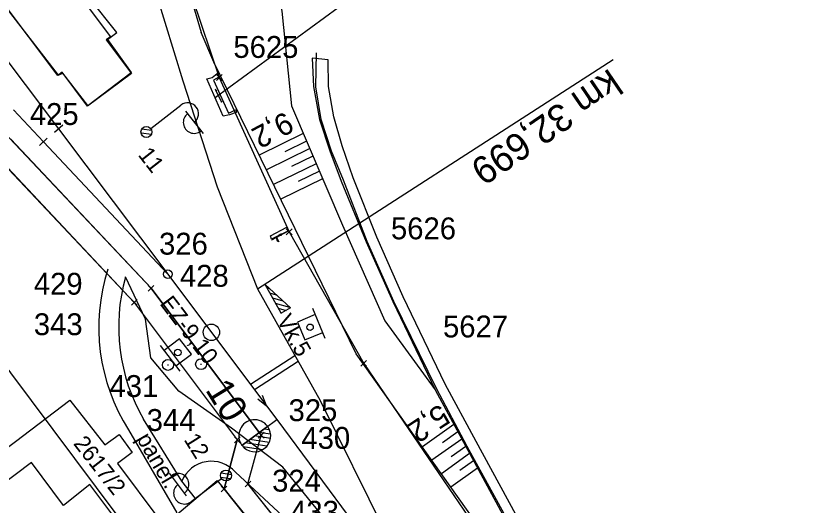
# Model space of a CAD drawing. Extents: x -804166 to -803706, y -1151030 to -1150147.
# Drawn here: x -803925.7 to -803852.1, y -1150474.2 to -1150429.4 of the extents above; entities that cross this region are included whole.
import ezdxf

# ---------------------------------------------------------------- set-up
doc = ezdxf.new("R2010")
doc.units = 0
for name, color, linetype in [('0381KM032-037P - Vrstva 1', 7, 'Continuous'), ('0381KM032-037P - Vrstva 13', 7, 'Continuous'), ('0381KM032-037P - Vrstva 17', 7, 'Continuous'), ('0381KM032-037P - Vrstva 19', 7, 'Continuous'), ('0381KM032-037P - Vrstva 2', 7, 'Continuous'), ('0381KM032-037P - Vrstva 23', 7, 'Continuous'), ('0381KM032-037P - Vrstva 25', 7, 'Continuous'), ('0381KM032-037P - Vrstva 27', 7, 'Continuous'), ('0381KM032-037P - Vrstva 3', 7, 'Continuous'), ('0381KM032-037P - Vrstva 48', 7, 'Continuous'), ('0381KM032-037P - Vrstva 49', 7, 'Continuous'), ('0381KM032-037P - Vrstva 51', 7, 'Continuous'), ('0381KM032-037P - Vrstva 55', 7, 'Continuous'), ('0381KM032-037P - Vrstva 57', 7, 'Continuous'), ('0381KM032-037P - Vrstva 7', 7, 'Continuous'), ('DZ_CD - CD', 7, 'Continuous'), ('DZ_CD - CD_krizek', 7, 'Continuous'), ('DZ_CD - CD_čísla', 7, 'Continuous'), ('szdc - hran DP', 7, 'Continuous'), ('szdc - szdc_cislo', 7, 'Continuous'), ('szdc - szdc_krizek', 7, 'Continuous'), ('VB - VB', 7, 'Continuous'), ('VB - VB_cislo', 7, 'Continuous'), ('VB - VB_krizek', 7, 'Continuous')]:
    doc.layers.add(name, color=color, linetype=linetype)

msp = doc.modelspace()

# ---------------------------------------------------------------- linework, layer by layer
at = {"layer": '0381KM032-037P - Vrstva 1'}
for p, q in [((-803925.981, -1150438.008), (-803923.249, -1150440.918)), ((-803901.897, -1150466.329), (-803893.522, -1150477.59))]:
    msp.add_line(p, q, dxfattribs=at)
for points in [[(-804011.14, -1150262.39), (-804005.45, -1150273.41), (-803998.73, -1150284.85), (-803991.51, -1150295.63), (-803978.8, -1150312.77), (-803963.69, -1150332.99), (-803952.21, -1150348.36), (-803946.3, -1150356.39), (-803941.6, -1150363.14), (-803936.71, -1150370.83), (-803932.05, -1150378.84), (-803927.78, -1150386.91), (-803924.06, -1150395.18), (-803920.62, -1150403.65), (-803918.06, -1150410.86), (-803915.07, -1150420.32), (-803912.96, -1150427.25), (-803910.49, -1150435.34), (-803907.334, -1150445.05), (-803903.668, -1150454.381), (-803897.938, -1150464.596), (-803891.973, -1150476.598)], [(-803975.617, -1150392.296), (-803939.473, -1150444.116), (-803928.265, -1150459.416), (-803914.534, -1150477.731)], [(-803937.129, -1150419.412), (-803921.855, -1150439.729)], [(-803921.855, -1150439.729), (-803911.864, -1150453.035), (-803902.83, -1150465.067), (-803901.897, -1150466.329)], [(-803923.249, -1150440.918), (-803911.864, -1150453.035), (-803902.83, -1150465.067), (-803901.897, -1150466.329)]]:
    msp.add_lwpolyline(points, dxfattribs=at)
at = {"layer": '0381KM032-037P - Vrstva 13'}
msp.add_lwpolyline([(-803875.883, -1150484.91), (-803874.859, -1150484.495), (-803883.662, -1150468.351), (-803886.496, -1150463.09), (-803890.342, -1150455.103), (-803892.739, -1150449.637), (-803894.892, -1150444.207), (-803895.921, -1150441.276), (-803896.676, -1150438.635), (-803897.147, -1150435.872), (-803897.2, -1150433.432), (-803898.654, -1150433.258), (-803898.54, -1150435.86), (-803897.995, -1150438.863), (-803897.041, -1150441.738), (-803895.987, -1150444.528), (-803893.704, -1150450.064), (-803891.289, -1150455.545), (-803887.412, -1150463.602)], close=True, dxfattribs=at)
at = {"layer": '0381KM032-037P - Vrstva 17'}
msp.add_line((-803911.209, -1150475.173), (-803907.336, -1150471.899), dxfattribs=at)
for points in [[(-803875.87, -1150484.459), (-803884.486, -1150468.8), (-803887.25, -1150463.566), (-803891.192, -1150455.528), (-803893.615, -1150450.032), (-803895.787, -1150444.436), (-803896.9, -1150441.761), (-803897.818, -1150438.885), (-803898.314, -1150435.883), (-803898.256, -1150432.783)], [(-803907.336, -1150471.899), (-803888.961, -1150494.568)]]:
    msp.add_lwpolyline(points, dxfattribs=at)
at = {"layer": '0381KM032-037P - Vrstva 19'}
for p, q in [((-803907.537, -1150436.866), (-803852.112, -1150396.222)), ((-803907.526, -1150436.102), (-803907.373, -1150436.242)), ((-803902.473, -1150449.514), (-803900.978, -1150448.743)), ((-803900.834, -1150449.068), (-803902.371, -1150449.816)), ((-803902.35, -1150449.879), (-803900.834, -1150449.068)), ((-803900.978, -1150448.743), (-803900.834, -1150449.068)), ((-803902.371, -1150449.816), (-803902.473, -1150449.514)), ((-803902.371, -1150449.816), (-803902.35, -1150449.879)), ((-803901.816, -1150449.998), (-803901.912, -1150449.697))]:
    msp.add_line(p, q, dxfattribs=at)
for points in [[(-803908.281, -1150435.147), (-803907.8, -1150435.023), (-803907.337, -1150434.681), (-803907.197, -1150434.991), (-803907.689, -1150435.265), (-803906.318, -1150438.295), (-803905.582, -1150437.956), (-803905.605, -1150438.249), (-803906.227, -1150438.463), (-803906.793, -1150438.584), (-803908.281, -1150435.147)], [(-803907.526, -1150436.102), (-803906.954, -1150437.281), (-803906.898, -1150437.161)], [(-803900.834, -1150449.068), (-803900.834, -1150449.068), (-803900.774, -1150449.197)], [(-803901.912, -1150449.697), (-803901.906, -1150449.663), (-803901.715, -1150450.066), (-803901.816, -1150449.998)]]:
    msp.add_lwpolyline(points, dxfattribs=at)
msp.add_ellipse((-803901.564, -1150449.426), major_axis=(0.129, 0.077), ratio=0.428282, dxfattribs=at)
at = {"layer": '0381KM032-037P - Vrstva 2'}
for p, q in [((-803921.481, -1150439.397), (-803922.229, -1150440.061)), ((-803921.855, -1150439.729), (-803911.864, -1150453.035)), ((-803922.888, -1150440.573), (-803923.61, -1150441.263)), ((-803905.077, -1150468.694), (-803901.897, -1150466.329)), ((-803905.085, -1150468.688), (-803902.731, -1150466.949)), ((-803902.453, -1150467.676), (-803903.501, -1150467.519)), ((-803902.551, -1150467.276), (-803903.068, -1150467.199)), ((-803902.579, -1150468.425), (-803904.366, -1150468.157)), ((-803902.467, -1150468.058), (-803903.933, -1150467.837)), ((-803905.084, -1150468.689), (-803905.085, -1150468.688)), ((-803903.204, -1150469.1), (-803904.955, -1150468.837)), ((-803902.804, -1150468.776), (-803904.798, -1150468.476))]:
    msp.add_line(p, q, dxfattribs=at)
for points in [[(-803923.249, -1150440.918), (-803911.864, -1150453.035), (-803901.897, -1150466.329)], [(-803903.617, -1150464.45), (-803902.83, -1150465.067), (-803903.203, -1150464.139)]]:
    msp.add_lwpolyline(points, dxfattribs=at)
msp.add_circle((-803911.864, -1150453.035), 0.4, dxfattribs=at)
for centre, radius, start, end in [((-803903.907, -1150467.817), 1.462, 36.40566, 216.87518), ((-803903.907, -1150467.818), 1.464, 216.49519, 36.45604)]:
    msp.add_arc(centre, radius, start, end, dxfattribs=at)
at = {"layer": '0381KM032-037P - Vrstva 23'}
for p, q in [((-803916.52, -1150430.915), (-803932.913, -1150410.127)), ((-803938.071, -1150413.885), (-803921.901, -1150434.824)), ((-803917.389, -1150431.545), (-803916.52, -1150430.915)), ((-803917.389, -1150431.545), (-803915.2, -1150434.565)), ((-803921.901, -1150434.824), (-803921.458, -1150434.637)), ((-803919.171, -1150437.591), (-803921.458, -1150434.637)), ((-803919.171, -1150437.591), (-803915.2, -1150434.565)), ((-803919.171, -1150437.591), (-803919.171, -1150437.591))]:
    msp.add_line(p, q, dxfattribs=at)
at = {"layer": '0381KM032-037P - Vrstva 25'}
for p, q in [((-803913.427, -1150439.714), (-803910.666, -1150437.563)), ((-803910.235, -1150438.115), (-803908.637, -1150440.166)), ((-803914.313, -1150440.101), (-803913.362, -1150440.219)), ((-803914.23, -1150439.734), (-803913.357, -1150439.842)), ((-803910.152, -1150473.302), (-803911.72, -1150471.228)), ((-803906.046, -1150471.376), (-803906.995, -1150471.244)), ((-803906.938, -1150471.75), (-803909.73, -1150473.861)), ((-803906.134, -1150471.742), (-803907.006, -1150471.621))]:
    msp.add_line(p, q, dxfattribs=at)
for centre in [(-803913.821, -1150440.021), (-803906.539, -1150471.449), (-803906.539, -1150471.449)]:
    msp.add_circle(centre, 0.5, dxfattribs=at)
for centre, start, end in [((-803910.051, -1150438.352), 307.9199, 127.9199), ((-803909.446, -1150439.148), 127.21733, 308.62248), ((-803910.926, -1150472.258), 306.37771, 127.78285), ((-803910.333, -1150473.063), 127.08028, 307.08028)]:
    msp.add_arc(centre, 1, start, end, dxfattribs=at)
at = {"layer": '0381KM032-037P - Vrstva 27'}
msp.add_line((-803908.868, -1150461.265), (-803908.768, -1150461.265), dxfattribs=at)
msp.add_circle((-803908.818, -1150461.265), 0.5, dxfattribs=at)
at = {"layer": '0381KM032-037P - Vrstva 3'}
for p, q in [((-803903.668, -1150454.381), (-803871.126, -1150433.376)), ((-803902.805, -1150454.284), (-803902.575, -1150454.349)), ((-803902.546, -1150454.747), (-803901.955, -1150454.913)), ((-803902.286, -1150455.209), (-803901.335, -1150455.477)), ((-803902.027, -1150455.672), (-803900.714, -1150456.041)), ((-803901.767, -1150456.134), (-803901.031, -1150456.341)), ((-803901.508, -1150456.596), (-803901.493, -1150456.601)), ((-803897.459, -1150458.912), (-803898.603, -1150456.186)), ((-803898.374, -1150456.731), (-803900.01, -1150457.418)), ((-803900.01, -1150457.418), (-803899.323, -1150459.053)), ((-803899.323, -1150459.053), (-803897.688, -1150458.367)), ((-803912.548, -1150459.549), (-803910.758, -1150461.903)), ((-803910.778, -1150458.946), (-803912.19, -1150460.02)), ((-803909.704, -1150460.358), (-803910.778, -1150458.946)), ((-803911.116, -1150461.432), (-803909.704, -1150460.358))]:
    msp.add_line(p, q, dxfattribs=at)
msp.add_lwpolyline([(-803902.97, -1150453.99), (-803900.63, -1150456.117), (-803901.503, -1150456.606), (-803902.97, -1150453.99)], dxfattribs=at)
for centre in [(-803898.85, -1150457.89), (-803910.945, -1150460.191)]:
    msp.add_circle(centre, 0.296, dxfattribs=at)
at = {"layer": '0381KM032-037P - Vrstva 48'}
for p, q in [((-803899.465, -1150440.159), (-803903.499, -1150442.127)), ((-803899.171, -1150440.85), (-803901.17, -1150441.826)), ((-803898.877, -1150441.541), (-803902.841, -1150443.475)), ((-803898.583, -1150442.232), (-803900.547, -1150443.191)), ((-803898.289, -1150442.923), (-803902.183, -1150444.823)), ((-803897.995, -1150443.614), (-803899.924, -1150444.556)), ((-803897.7, -1150444.305), (-803901.525, -1150446.172)), ((-803885.686, -1150466.792), (-803888.569, -1150468.841)), ((-803885.327, -1150467.456), (-803886.73, -1150468.454)), ((-803884.967, -1150468.121), (-803887.7, -1150470.063)), ((-803884.607, -1150468.786), (-803885.936, -1150469.73)), ((-803884.248, -1150469.45), (-803886.831, -1150471.286)), ((-803883.888, -1150470.115), (-803885.142, -1150471.006)), ((-803883.529, -1150470.779), (-803885.962, -1150472.509))]:
    msp.add_line(p, q, dxfattribs=at)
at = {"layer": '0381KM032-037P - Vrstva 49'}
for points in [[(-804010.873, -1150255.863), (-804001.608, -1150274.672), (-803994.699, -1150286.679), (-803981.461, -1150304.357), (-803936.046, -1150366.093), (-803921.768, -1150392.538), (-803912.222, -1150419.282), (-803908.812, -1150430.908)], [(-803920.94, -1150376.21), (-803910.018, -1150390.511), (-803912.553, -1150396.059), (-803903.866, -1150412.95), (-803903.684, -1150418.644), (-803901.421, -1150428.97), (-803900.537, -1150437.639), (-803895.89, -1150448.56), (-803892.01, -1150457.3), (-803887.412, -1150463.602), (-803875.883, -1150484.91), (-803874.859, -1150484.495), (-803872.322, -1150492.497), (-803872.997, -1150496.546), (-803874.041, -1150498.946)], [(-803877.416, -1150484.532), (-803894.615, -1150460.334), (-803907.648, -1150433.624), (-803908.812, -1150430.908)]]:
    msp.add_lwpolyline(points, dxfattribs=at)
at = {"layer": '0381KM032-037P - Vrstva 51'}
for p, q in [((-803915.743, -1150453.306), (-803915.72, -1150453.288)), ((-803915.449, -1150467.279), (-803911.051, -1150474.867)), ((-803900.893, -1150475.608), (-803905.683, -1150471.142))]:
    msp.add_line(p, q, dxfattribs=at)
for points in [[(-803881.519, -1150497.913), (-803892.597, -1150481.46), (-803901.351, -1150470.694), (-803906.021, -1150467.127), (-803910.842, -1150463.746), (-803913.43, -1150460.674), (-803913.908, -1150457.138), (-803915.72, -1150453.288)], [(-803909.318, -1150473.555), (-803910.58, -1150471.975), (-803914.083, -1150466.31)]]:
    msp.add_lwpolyline(points, dxfattribs=at)
for centre, major_axis, ratio, start_param, end_param in [((-803900.854, -1150457.933), (3.992, -16.878), 0.999168, 4.166515, 5.049488), ((-803899.462, -1150457.838), (3.305, -16.585), 0.999136, 4.244568, 5.04061), ((-803907.875, -1150473.065), (-1.906, 2.208), 0.999734, 4.72036, 6.75861)]:
    msp.add_ellipse(centre, major_axis=major_axis, ratio=ratio, start_param=start_param, end_param=end_param, dxfattribs=at)
at = {"layer": '0381KM032-037P - Vrstva 55'}
msp.add_lwpolyline([(-803937.77, -1150413.78), (-803932.96, -1150410.23), (-803917.09, -1150431.3), (-803917.49, -1150431.6), (-803915.17, -1150434.66), (-803919.22, -1150437.65), (-803921.53, -1150434.55), (-803921.93, -1150434.85)], close=True, dxfattribs=at)
msp.add_lwpolyline([(-803914.71, -1150478.01), (-803919.01, -1150472.26), (-803921.41, -1150474.2), (-803924.33, -1150470.27), (-803930.11, -1150474.6), (-803931.57, -1150472.66), (-803925.79, -1150468.33), (-803920.83, -1150464.56), (-803917.63, -1150468.64), (-803916.3, -1150467.69), (-803915.12, -1150469.35), (-803916.46, -1150470.34), (-803904.84, -1150485.91), (-803905.5, -1150486.41)], dxfattribs=at)
at = {"layer": '0381KM032-037P - Vrstva 7'}
for p, q in [((-803900.24, -1150460.491), (-803904.286, -1150463.128)), ((-803899.946, -1150461.016), (-803903.925, -1150463.609)), ((-803911.896, -1150461.333), (-803911.796, -1150461.333))]:
    msp.add_line(p, q, dxfattribs=at)
for centre, radius in [((-803907.873, -1150458.35), 0.75), ((-803911.846, -1150461.333), 0.5)]:
    msp.add_circle(centre, radius, dxfattribs=at)
at = {"layer": 'DZ_CD - CD'}
for p, q in [((-803913.398, -1150454.324), (-803936.111, -1150430.295)), ((-803937.526, -1150431.71), (-803914.931, -1150455.612)), ((-803903.322, -1150467.763), (-803913.398, -1150454.324)), ((-803914.931, -1150455.612), (-803905.507, -1150468.183)), ((-803905.507, -1150468.183), (-803906.72, -1150472.679)), ((-803904.526, -1150472.225), (-803903.322, -1150467.763)), ((-803906.72, -1150472.679), (-803885.328, -1150499.572)), ((-803883.675, -1150498.437), (-803904.526, -1150472.225))]:
    msp.add_line(p, q, dxfattribs=at)
at = {"layer": 'DZ_CD - CD_krizek'}
for p, q in [((-803913.133, -1150454.589), (-803913.664, -1150454.059)), ((-803913.664, -1150454.589), (-803913.133, -1150454.059)), ((-803914.666, -1150455.877), (-803915.197, -1150455.347)), ((-803915.197, -1150455.877), (-803914.666, -1150455.347)), ((-803903.057, -1150468.028), (-803903.588, -1150467.498)), ((-803903.588, -1150468.028), (-803903.057, -1150467.498)), ((-803905.242, -1150468.448), (-803905.773, -1150467.918)), ((-803905.773, -1150468.448), (-803905.242, -1150467.918)), ((-803904.261, -1150472.49), (-803904.792, -1150471.96)), ((-803904.792, -1150472.49), (-803904.261, -1150471.96)), ((-803906.455, -1150472.944), (-803906.986, -1150472.414)), ((-803906.986, -1150472.944), (-803906.455, -1150472.414))]:
    msp.add_line(p, q, dxfattribs=at)
at = {"layer": 'szdc - hran DP'}
for p, q in [((-803909.89, -1150426.9), (-803907.15, -1150435.03)), ((-803907.15, -1150435.03), (-803900.76, -1150449.16)), ((-803900.76, -1150449.16), (-803893.94, -1150461.19)), ((-803893.94, -1150461.19), (-803877.95, -1150484.62))]:
    msp.add_line(p, q, dxfattribs=at)
at = {"layer": 'szdc - szdc_krizek'}
for p, q in [((-803906.885, -1150435.295), (-803907.416, -1150434.765)), ((-803907.416, -1150435.295), (-803906.885, -1150434.765)), ((-803900.495, -1150449.425), (-803901.026, -1150448.895)), ((-803901.026, -1150449.425), (-803900.495, -1150448.895)), ((-803893.675, -1150461.455), (-803894.206, -1150460.925)), ((-803894.206, -1150461.455), (-803893.675, -1150460.925))]:
    msp.add_line(p, q, dxfattribs=at)
at = {"layer": 'VB - VB'}
for p, q in [((-803926.228, -1150440.668), (-803913.398, -1150454.324)), ((-803927.681, -1150442.042), (-803914.931, -1150455.612)), ((-803913.398, -1150454.324), (-803903.322, -1150467.763)), ((-803914.931, -1150455.612), (-803905.507, -1150468.183))]:
    msp.add_line(p, q, dxfattribs=at)
for points in [[(-803885.328, -1150499.572), (-803906.72, -1150472.679), (-803905.507, -1150468.183)], [(-803883.675, -1150498.437), (-803904.526, -1150472.225), (-803903.322, -1150467.763)]]:
    msp.add_lwpolyline(points, dxfattribs=at)
at = {"layer": 'VB - VB_krizek'}
for p, q in [((-803913.133, -1150454.589), (-803913.664, -1150454.059)), ((-803913.664, -1150454.589), (-803913.133, -1150454.059)), ((-803914.666, -1150455.877), (-803915.197, -1150455.347)), ((-803915.197, -1150455.877), (-803914.666, -1150455.347)), ((-803903.057, -1150468.028), (-803903.588, -1150467.498)), ((-803903.588, -1150468.028), (-803903.057, -1150467.498)), ((-803905.242, -1150468.448), (-803905.773, -1150467.918)), ((-803905.773, -1150468.448), (-803905.242, -1150467.918)), ((-803904.261, -1150472.49), (-803904.792, -1150471.96)), ((-803904.792, -1150472.49), (-803904.261, -1150471.96)), ((-803906.455, -1150472.944), (-803906.986, -1150472.414)), ((-803906.986, -1150472.944), (-803906.455, -1150472.414))]:
    msp.add_line(p, q, dxfattribs=at)

# ---------------------------------------------------------------- texts
at = {"layer": '0381KM032-037P - Vrstva 2'}
msp.add_text('10', height=2.5, rotation=301.47562, dxfattribs=at).set_placement((-803908.478, -1150463.606))
at = {"layer": '0381KM032-037P - Vrstva 25'}
for s, rotation, p in [('11', 307.9199, (-803914.644, -1150442.133)), ('12', 302.08028, (-803910.438, -1150468.167))]:
    msp.add_text(s, height=1.5, rotation=rotation, dxfattribs=at).set_placement(p)
at = {"layer": '0381KM032-037P - Vrstva 3'}
for s, height, rotation, p in [('km 32,699', 2.5, 214.2898, (-803871.457, -1150434.149)), ('EZ-9,10', 1.5, 307.24913, (-803912.657, -1150455.735)), ('Vk.5', 1.5, 299.2898, (-803901.935, -1150457.221))]:
    msp.add_text(s, height=height, rotation=rotation, dxfattribs=at).set_placement(p)
at = {"layer": '0381KM032-037P - Vrstva 48'}
for s, rotation, p in [('9,2', 208.05026, (-803901.085, -1150438.096)), ('5,2', 213.41624, (-803886.957, -1150464.841))]:
    msp.add_text(s, height=2, rotation=rotation, dxfattribs=at).set_placement(p)
at = {"layer": '0381KM032-037P - Vrstva 51'}
msp.add_text('panel.', height=1.5, rotation=300.09655, dxfattribs=at).set_placement((-803914.767, -1150468.073))
at = {"layer": '0381KM032-037P - Vrstva 57'}
msp.add_text('2617/2', height=1.5, rotation=308.0366, dxfattribs=at).set_placement((-803920.561, -1150468.55))
at = {"layer": 'DZ_CD - CD_čísla'}
for s, p in [('326', (-803912.661, -1150451.241)), ('343', (-803924.117, -1150458.611)), ('325', (-803900.816, -1150466.478)), ('344', (-803913.794, -1150467.374)), ('324', (-803902.316, -1150472.926))]:
    msp.add_text(s, height=2, dxfattribs=at).set_placement(p)
at = {"layer": 'szdc - szdc_cislo'}
for s, p in [('5625', (-803905.864, -1150433.242)), ('5626', (-803891.446, -1150449.841)), ('5627', (-803886.684, -1150458.816))]:
    msp.add_text(s, height=2, dxfattribs=at).set_placement(p)
at = {"layer": 'VB - VB_cislo'}
for s, p in [('425', (-803924.485, -1150439.378)), ('428', (-803910.751, -1150454.179)), ('429', (-803924.119, -1150454.907)), ('431', (-803917.196, -1150464.267)), ('430', (-803899.638, -1150469.012)), ('433', (-803900.674, -1150475.769))]:
    msp.add_text(s, height=2, dxfattribs=at).set_placement(p)

doc.saveas('drawing.dxf')
